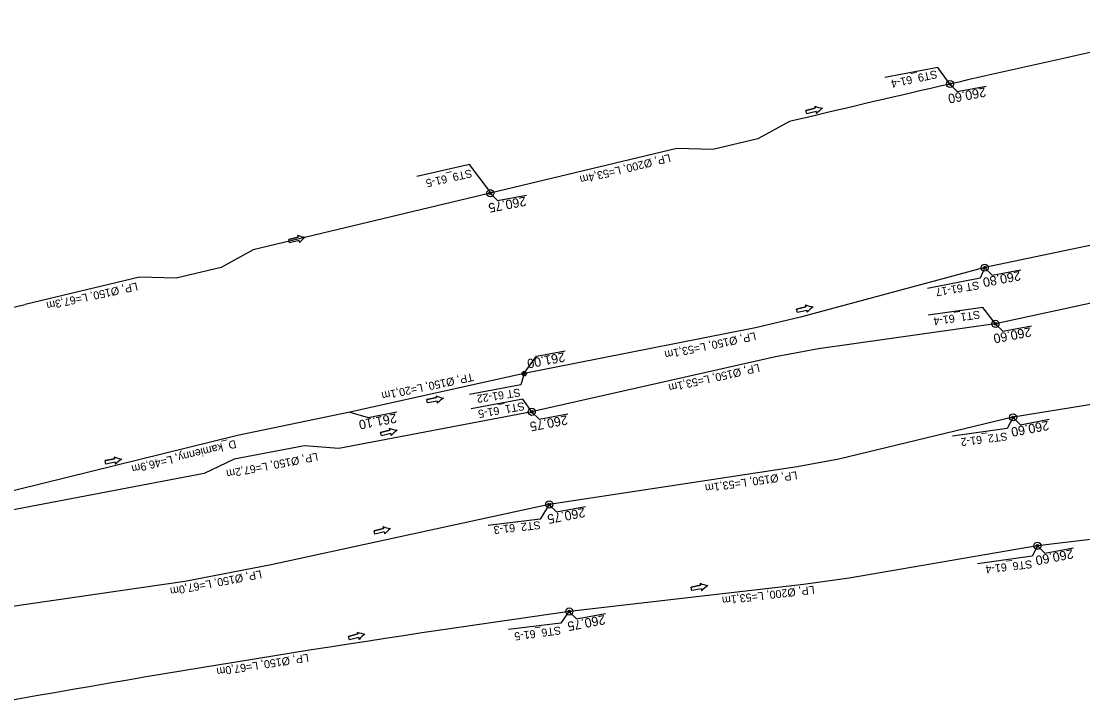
# Model space of a CAD drawing. Extents: x -1 to 65640748, y -22 to 5530284.
# Drawn here: x 6557749.5 to 6557868.8, y 5528716.5 to 5528793.4 of the extents above; entities that cross this region are included whole.
import ezdxf

# ---------------------------------------------------------------- set-up
doc = ezdxf.new("R2010")
doc.units = 0
for name, color, linetype in [('TOR_PS_ODW-drenaze', 7, 'Continuous'), ('TOR_PS_ODW-drenokolektory', 7, 'Continuous'), ('TOR_PS_ODW-studnie PEHD', 7, 'Continuous'), ('TOR_PS_OPIS_O-opisy rurociagow', 7, 'Continuous'), ('TOR_PS_OPIS_O-opisy studni', 7, 'Continuous'), ('TOR_PS_OPIS_T-INFO', 7, 'Continuous')]:
    doc.layers.add(name, color=color, linetype=linetype)

msp = doc.modelspace()

# ---------------------------------------------------------------- linework, layer by layer
at = {"layer": 'TOR_PS_ODW-drenaze'}
for points in [[(6557806.06, 5528753.84), (6557786.46, 5528749.51)], [(6557786.46, 5528749.51), (6557773.81, 5528746.9), (6557740.81, 5528738.76)]]:
    msp.add_lwpolyline(points, dxfattribs=at)
at = {"layer": 'TOR_PS_ODW-drenokolektory'}
for points in [[(6557836.8, 5528782.38), (6557835.89, 5528782.16), (6557832.33, 5528780.23), (6557827.27, 5528779.02), (6557823.23, 5528779.13), (6557802.22, 5528774.11)], [(6557916.64, 5528777.68), (6557896.13, 5528772.73), (6557894.25, 5528772.38), (6557890.76, 5528772.64), (6557857.83, 5528765.75)], [(6557802.22, 5528774.11), (6557775.58, 5528767.74), (6557771.97, 5528765.78), (6557766.91, 5528764.57), (6557762.81, 5528764.69), (6557749.94, 5528761.61)], [(6557917.98, 5528770.6), (6557900.05, 5528768.17), (6557895.23, 5528767.26), (6557859.03, 5528759.43)], [(6557857.83, 5528765.75), (6557837.13, 5528760.2), (6557832.07, 5528758.99), (6557806.06, 5528753.84)], [(6557919.99, 5528760.09), (6557902.39, 5528755.79), (6557897.59, 5528754.88), (6557861.02, 5528748.93), (6557861, 5528748.93)], [(6557859, 5528759.43), (6557839.14, 5528756.63), (6557834.32, 5528755.71), (6557806.88, 5528749.54)], [(6557806.88, 5528749.54), (6557806.9, 5528749.55), (6557785.22, 5528745.44), (6557781.37, 5528745.73), (6557773.44, 5528744.23), (6557770.08, 5528742.6), (6557741.12, 5528737.11), (6557741.1, 5528737.11)], [(6557860.99, 5528748.93), (6557841.41, 5528744.23), (6557836.75, 5528743.35), (6557808.87, 5528739.14)], [(6557923.16, 5528743.24), (6557904.08, 5528739.54), (6557898.95, 5528738.68), (6557863.75, 5528734.5)], [(6557808.87, 5528739.14), (6557808.87, 5528739.14), (6557777.59, 5528732.34), (6557767.89, 5528730.5), (6557743.06, 5528726.88)], [(6557863.73, 5528734.5), (6557842.58, 5528730.87), (6557837.44, 5528730.14), (6557811.13, 5528727.11)]]:
    msp.add_lwpolyline(points, dxfattribs=at)
for centre, radius, start, end in [((6558244.42, 5527077.53), 1752.9, 101.79237, 102.8726), ((6558244.42, 5527077.53), 1752.9, 102.8726, 103.44657), ((6557250.66, 5530849.85), 2147.1, 283.09267, 283.44657), ((6558049.42, 5527026.62), 1717.1, 97.97692, 100.21165)]:
    msp.add_arc(centre, radius, start, end, dxfattribs=at)
at = {"layer": 'TOR_PS_ODW-studnie PEHD'}
for centre, radius in [((6557853.92, 5528786.38), 0.4), ((6557853.92, 5528786.38), 0.145), ((6557802.24, 5528774.11), 0.4), ((6557802.24, 5528774.11), 0.145), ((6557857.83, 5528765.75), 0.4), ((6557857.83, 5528765.75), 0.145), ((6557859.03, 5528759.43), 0.4), ((6557859.03, 5528759.43), 0.145), ((6557806.06, 5528753.84), 0.25), ((6557806.06, 5528753.84), 0.112), ((6557806.9, 5528749.55), 0.4), ((6557806.9, 5528749.55), 0.145), ((6557861.02, 5528748.93), 0.4), ((6557861.02, 5528748.93), 0.145), ((6557808.87, 5528739.14), 0.4), ((6557808.87, 5528739.14), 0.145), ((6557863.75, 5528734.5), 0.4), ((6557863.75, 5528734.5), 0.145), ((6557811.13, 5528727.11), 0.4), ((6557811.13, 5528727.11), 0.145)]:
    msp.add_circle(centre, radius, dxfattribs=at)
at = {"layer": 'TOR_PS_OPIS_O-opisy rurociagow'}
for p, q in [((6557837.72, 5528783.42), (6557838.78, 5528783.67)), ((6557838.78, 5528783.67), (6557837.72, 5528783.42)), ((6557837.81, 5528783.03), (6557837.72, 5528783.42)), ((6557837.81, 5528783.03), (6557837.72, 5528783.42)), ((6557838.88, 5528783.28), (6557837.81, 5528783.03)), ((6557838.88, 5528783.28), (6557837.81, 5528783.03)), ((6557779.58, 5528768.91), (6557780.64, 5528769.18)), ((6557780.64, 5528769.18), (6557779.58, 5528768.91)), ((6557779.68, 5528768.52), (6557779.58, 5528768.91)), ((6557779.68, 5528768.52), (6557779.58, 5528768.91)), ((6557780.74, 5528768.79), (6557779.68, 5528768.52)), ((6557780.74, 5528768.79), (6557779.68, 5528768.52)), ((6557836.67, 5528761.07), (6557837.73, 5528761.34)), ((6557837.73, 5528761.34), (6557836.67, 5528761.07)), ((6557836.77, 5528760.69), (6557836.67, 5528761.07)), ((6557836.77, 5528760.69), (6557836.67, 5528761.07)), ((6557837.83, 5528760.95), (6557836.77, 5528760.69)), ((6557837.83, 5528760.95), (6557836.77, 5528760.69)), ((6557795.11, 5528750.94), (6557796.19, 5528751.14)), ((6557796.19, 5528751.14), (6557795.11, 5528750.94)), ((6557795.18, 5528750.55), (6557795.11, 5528750.94)), ((6557795.18, 5528750.55), (6557795.11, 5528750.94)), ((6557796.26, 5528750.75), (6557795.18, 5528750.55)), ((6557796.26, 5528750.75), (6557795.18, 5528750.55)), ((6557789.9, 5528747.23), (6557790.96, 5528747.5)), ((6557790.96, 5528747.5), (6557789.9, 5528747.23)), ((6557790, 5528746.84), (6557789.9, 5528747.23)), ((6557790, 5528746.84), (6557789.9, 5528747.23)), ((6557791.06, 5528747.11), (6557790, 5528746.84)), ((6557791.06, 5528747.11), (6557790, 5528746.84)), ((6557758.93, 5528744.08), (6557760.01, 5528744.28)), ((6557760.01, 5528744.28), (6557758.93, 5528744.08)), ((6557759.01, 5528743.68), (6557758.93, 5528744.08)), ((6557759.01, 5528743.68), (6557758.93, 5528744.08)), ((6557760.08, 5528743.89), (6557759.01, 5528743.68)), ((6557760.08, 5528743.89), (6557759.01, 5528743.68)), ((6557789.17, 5528736.18), (6557790.23, 5528736.45)), ((6557790.23, 5528736.45), (6557789.17, 5528736.18)), ((6557789.27, 5528735.79), (6557789.17, 5528736.18)), ((6557789.27, 5528735.79), (6557789.17, 5528736.18)), ((6557790.33, 5528736.06), (6557789.27, 5528735.79)), ((6557790.33, 5528736.06), (6557789.27, 5528735.79)), ((6557824.83, 5528729.86), (6557825.9, 5528730.06)), ((6557825.9, 5528730.06), (6557824.83, 5528729.86)), ((6557824.9, 5528729.46), (6557824.83, 5528729.86)), ((6557824.9, 5528729.46), (6557824.83, 5528729.86)), ((6557825.97, 5528729.67), (6557824.9, 5528729.46)), ((6557825.97, 5528729.67), (6557824.9, 5528729.46)), ((6557786.3, 5528724.32), (6557787.36, 5528724.59)), ((6557787.36, 5528724.59), (6557786.3, 5528724.32)), ((6557786.4, 5528723.93), (6557786.3, 5528724.32)), ((6557786.4, 5528723.93), (6557786.3, 5528724.32)), ((6557787.46, 5528724.2), (6557786.4, 5528723.93)), ((6557787.46, 5528724.2), (6557786.4, 5528723.93))]:
    msp.add_line(p, q, dxfattribs=at)
for points in [[(6557838.72, 5528783.88), (6557838.72, 5528783.88)], [(6557838.92, 5528783.06), (6557838.92, 5528783.06)], [(6557780.58, 5528769.39), (6557780.58, 5528769.39)], [(6557780.78, 5528768.57), (6557780.78, 5528768.57)], [(6557837.67, 5528761.56), (6557837.67, 5528761.56)], [(6557837.88, 5528760.73), (6557837.88, 5528760.73)], [(6557796.14, 5528751.36), (6557796.14, 5528751.36)], [(6557796.29, 5528750.52), (6557796.29, 5528750.52)], [(6557790.9, 5528747.71), (6557790.9, 5528747.71)], [(6557791.1, 5528746.89), (6557791.1, 5528746.89)], [(6557759.95, 5528744.5), (6557759.95, 5528744.5)], [(6557760.11, 5528743.66), (6557760.11, 5528743.66)], [(6557790.16, 5528736.66), (6557790.16, 5528736.66)], [(6557790.37, 5528735.84), (6557790.37, 5528735.84)], [(6557825.85, 5528730.28), (6557825.85, 5528730.28)], [(6557826.01, 5528729.45), (6557826.01, 5528729.45)], [(6557787.3, 5528724.8), (6557787.3, 5528724.8)], [(6557787.5, 5528723.98), (6557787.5, 5528723.98)]]:
    msp.add_lwpolyline(points, dxfattribs=at)
for centre, radius, start, end in [((6557839.18, 5528783.9), 0.458, 181.7727, 210.234), ((6557840.43, 5528788.5), 4.92, 249.6582, 260.04), ((6557840.43, 5528788.5), 4.92, 249.6582, 260.04), ((6557839.18, 5528783.9), 0.458, 181.7727, 210.234), ((6557839.33, 5528783.25), 0.458, 176.5021, 204.9633), ((6557839.33, 5528783.25), 0.458, 176.5021, 204.9633), ((6557842.52, 5528779.71), 4.92, 126.696, 137.0779), ((6557842.52, 5528779.71), 4.92, 126.696, 137.0779), ((6557781.03, 5528769.41), 0.458, 182.433, 210.8942), ((6557782.23, 5528774.02), 4.92, 250.3184, 260.7002), ((6557782.23, 5528774.02), 4.92, 250.3184, 260.7002), ((6557781.03, 5528769.41), 0.458, 182.433, 210.8942), ((6557781.19, 5528768.77), 0.458, 177.1623, 205.6236), ((6557781.19, 5528768.77), 0.458, 177.1623, 205.6236), ((6557784.42, 5528765.26), 4.92, 127.3563, 137.7381), ((6557784.42, 5528765.26), 4.92, 127.3563, 137.7381), ((6557838.13, 5528761.57), 0.458, 182.433, 210.8942), ((6557839.33, 5528766.19), 4.92, 250.3184, 260.7002), ((6557839.33, 5528766.19), 4.92, 250.3184, 260.7002), ((6557838.13, 5528761.57), 0.458, 182.433, 210.8942), ((6557841.51, 5528757.42), 4.92, 127.3563, 137.7381), ((6557841.51, 5528757.42), 4.92, 127.3563, 137.7381), ((6557838.29, 5528760.93), 0.458, 177.1623, 205.6236), ((6557838.29, 5528760.93), 0.458, 177.1623, 205.6236), ((6557796.6, 5528751.35), 0.458, 178.6495, 207.1107), ((6557798.1, 5528755.87), 4.92, 246.5349, 256.9167), ((6557798.1, 5528755.87), 4.92, 246.5349, 256.9167), ((6557796.6, 5528751.35), 0.458, 178.6495, 207.1107), ((6557796.71, 5528750.69), 0.458, 173.3788, 201.8401), ((6557796.71, 5528750.69), 0.458, 173.3788, 201.8401), ((6557799.7, 5528746.98), 4.92, 123.5728, 133.9546), ((6557799.7, 5528746.98), 4.92, 123.5728, 133.9546), ((6557791.35, 5528747.73), 0.458, 182.433, 210.8942), ((6557792.55, 5528752.34), 4.92, 250.3184, 260.7002), ((6557792.55, 5528752.34), 4.92, 250.3184, 260.7002), ((6557791.35, 5528747.73), 0.458, 182.433, 210.8942), ((6557791.52, 5528747.09), 0.458, 177.1623, 205.6236), ((6557791.52, 5528747.09), 0.458, 177.1623, 205.6236), ((6557794.74, 5528743.58), 4.92, 127.3563, 137.7381), ((6557794.74, 5528743.58), 4.92, 127.3563, 137.7381), ((6557760.41, 5528744.49), 0.458, 179.1068, 207.5681), ((6557761.88, 5528749.02), 4.92, 246.9923, 257.3741), ((6557761.88, 5528749.02), 4.92, 246.9923, 257.3741), ((6557760.41, 5528744.49), 0.458, 179.1068, 207.5681), ((6557760.54, 5528743.84), 0.458, 173.8362, 202.2974), ((6557760.54, 5528743.84), 0.458, 173.8362, 202.2974), ((6557763.55, 5528740.15), 4.92, 124.0302, 134.412), ((6557763.55, 5528740.15), 4.92, 124.0302, 134.412), ((6557790.62, 5528736.68), 0.458, 182.433, 210.8942), ((6557791.82, 5528741.29), 4.92, 250.3184, 260.7002), ((6557791.82, 5528741.29), 4.92, 250.3184, 260.7002), ((6557790.62, 5528736.68), 0.458, 182.433, 210.8942), ((6557794.01, 5528732.53), 4.92, 127.3563, 137.7381), ((6557794.01, 5528732.53), 4.92, 127.3563, 137.7381), ((6557790.78, 5528736.03), 0.458, 177.1623, 205.6236), ((6557790.78, 5528736.03), 0.458, 177.1623, 205.6236), ((6557826.3, 5528730.28), 0.458, 179.3379, 207.7991), ((6557827.75, 5528734.82), 4.92, 247.2233, 257.6051), ((6557827.75, 5528734.82), 4.92, 247.2233, 257.6051), ((6557826.3, 5528730.28), 0.458, 179.3379, 207.7991), ((6557826.43, 5528729.62), 0.458, 174.0672, 202.5285), ((6557826.43, 5528729.62), 0.458, 174.0672, 202.5285), ((6557829.46, 5528725.95), 4.92, 124.2612, 134.643), ((6557829.46, 5528725.95), 4.92, 124.2612, 134.643), ((6557787.75, 5528724.82), 0.458, 182.433, 210.8942), ((6557788.95, 5528729.43), 4.92, 250.3184, 260.7002), ((6557788.95, 5528729.43), 4.92, 250.3184, 260.7002), ((6557787.75, 5528724.82), 0.458, 182.433, 210.8942), ((6557787.92, 5528724.18), 0.458, 177.1623, 205.6236), ((6557787.92, 5528724.18), 0.458, 177.1623, 205.6236), ((6557791.14, 5528720.67), 4.92, 127.3563, 137.7381), ((6557791.14, 5528720.67), 4.92, 127.3563, 137.7381)]:
    msp.add_arc(centre, radius, start, end, dxfattribs=at)
at = {"layer": 'TOR_PS_OPIS_T-INFO'}
for points in [[(6557853.93, 5528786.34), (6557852.56, 5528788.24), (6557846.61, 5528787.1)], [(6557853.88, 5528786.39), (6557854.74, 5528785.55), (6557857.98, 5528786.15)], [(6557802.21, 5528774.25), (6557799.91, 5528777.33), (6557794, 5528776)], [(6557802.21, 5528774.12), (6557803.06, 5528773.28), (6557806.3, 5528773.88)], [(6557857.83, 5528765.75), (6557857.33, 5528764.55), (6557851.38, 5528763.41)], [(6557857.79, 5528765.76), (6557858.65, 5528764.92), (6557861.89, 5528765.52)], [(6557859.03, 5528759.43), (6557857.62, 5528761.27), (6557851.47, 5528760.4)], [(6557858.99, 5528759.44), (6557859.85, 5528758.6), (6557863.08, 5528759.2)], [(6557806.04, 5528753.9), (6557807.42, 5528755.79), (6557810.66, 5528756.39)], [(6557806.06, 5528753.84), (6557805.69, 5528752.57), (6557799.9, 5528751.49)], [(6557806.9, 5528749.55), (6557805.89, 5528750.97), (6557800.1, 5528749.89)], [(6557786.46, 5528749.51), (6557788.5, 5528748.92), (6557791.74, 5528749.53)], [(6557806.86, 5528749.56), (6557807.72, 5528748.72), (6557810.96, 5528749.32)], [(6557861.02, 5528748.93), (6557860.34, 5528747.69), (6557854.19, 5528746.82)], [(6557860.98, 5528748.94), (6557861.84, 5528748.1), (6557865.07, 5528748.71)], [(6557808.87, 5528739.14), (6557807.84, 5528737.48), (6557801.99, 5528736.76)], [(6557808.83, 5528739.15), (6557809.69, 5528738.31), (6557812.93, 5528738.92)], [(6557863.75, 5528734.5), (6557863.16, 5528733.33), (6557857.02, 5528732.47)], [(6557863.72, 5528734.51), (6557864.57, 5528733.67), (6557867.81, 5528734.27)], [(6557811.09, 5528727.12), (6557810.16, 5528725.8), (6557804.3, 5528725.08)], [(6557811.09, 5528727.12), (6557811.95, 5528726.28), (6557815.19, 5528726.88)]]:
    msp.add_lwpolyline(points, dxfattribs=at)

# ---------------------------------------------------------------- texts
at = {"layer": 'TOR_PS_OPIS_O-opisy rurociagow'}
for s, rotation, p in [('LP, Ø200, L=53,4m', 193.8471, (6557822.39, 5528778.53)), ('LP, Ø150, L=67,3m', 192.2403, (6557762.5, 5528764.09)), ('LP, Ø150, L=53,1m', 191.8818, (6557832.01, 5528758.51)), ('LP, Ø150, L=53,1m', 192.6807, (6557832.42, 5528754.95)), ('TP, Ø150, L=20,1m', 191.8818, (6557800.26, 5528753.91)), ('D_kamienny, L=46,9m', 193.8549, (6557773.56, 5528746.4)), ('LP, Ø150, L=67,2m', 190.9039, (6557782.78, 5528744.96)), ('LP, Ø150, L=53,1m', 188.1208, (6557836.69, 5528742.87)), ('LP, Ø150, L=67,0m', 190.9039, (6557776.46, 5528731.76)), ('LP, Ø200, L=53,1m', 186.7808, (6557838.64, 5528730.01)), ('LP, Ø150, L=67,0m', 188.7917, (6557781.76, 5528722.37))]:
    msp.add_text(s, height=0.9, rotation=rotation, dxfattribs=at).set_placement(p)
at = {"layer": 'TOR_PS_OPIS_O-opisy studni'}
for s, rotation, p in [('ST9_61-4', 192.4503, (6557852.38, 5528787.95)), ('ST9_61-5', 192.7969, (6557800.08, 5528776.81)), ('ST 61-17', 189.424, (6557857.13, 5528764.22)), ('ST1_61-4', 188.7159, (6557857.23, 5528760.94)), ('ST 61-22', 188.7062, (6557805.56, 5528752.18)), ('ST1_61-5', 190.0911, (6557806.01, 5528750.65)), ('ST2_61-2', 187.4015, (6557860.32, 5528747.25)), ('ST2_61-3', 186.316, (6557807.84, 5528737.28)), ('ST6_61-4', 186.7584, (6557863.11, 5528732.89)), ('ST6_61-5', 187.7955, (6557810.12, 5528725.45))]:
    msp.add_text(s, height=0.9, rotation=rotation, dxfattribs=at).set_placement(p)
at = {"layer": 'TOR_PS_OPIS_T-INFO'}
for s, p in [('260.60', (6557857.85, 5528786.01)), ('260.75', (6557806.17, 5528773.74)), ('260.80', (6557861.76, 5528765.38)), ('260.60', (6557862.95, 5528759.06)), ('261.00', (6557810.53, 5528756.24)), ('261.10', (6557791.61, 5528749.38)), ('260.75', (6557810.83, 5528749.17)), ('260.60', (6557864.94, 5528748.56)), ('260.75', (6557812.8, 5528738.77)), ('260.60', (6557867.68, 5528734.13)), ('260.75', (6557815.06, 5528726.73))]:
    msp.add_text(s, height=1.05, rotation=190.7506, dxfattribs=at).set_placement(p)

doc.saveas('drawing.dxf')
